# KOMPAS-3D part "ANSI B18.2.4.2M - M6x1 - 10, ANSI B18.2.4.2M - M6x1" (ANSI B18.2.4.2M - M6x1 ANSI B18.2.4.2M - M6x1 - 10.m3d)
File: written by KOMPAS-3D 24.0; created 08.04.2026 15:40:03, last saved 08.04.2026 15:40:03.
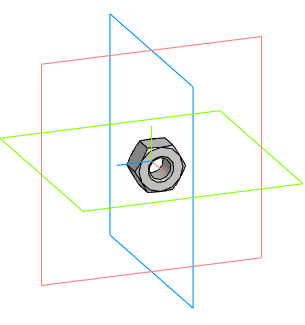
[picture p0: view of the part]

Document properties: Автор: R2D2; Полное имя файла: E:\Работа\Зайцев\VSO1121M-F-S Клапан запорный сальниковый DN.ru\DN15\исходные материалы\ANSI B18.2.4.2M - M6x1 ANSI B18.2.4.2M - M6x1 - 10.m3d

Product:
- Body: Solid1  | qty 1
- Part/product: ANSI B18.2.4.2M - M6x1 - 10  | designation ANSI B18.2.4.2M - M6x1
    Комментарий: Типы метрических   шестигранных гаек   2
    additional columns: Сталь, мягкая

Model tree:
1. Solid1  (labels: Solid1)

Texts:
  ANSI B18.2.4.2M - M6x1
